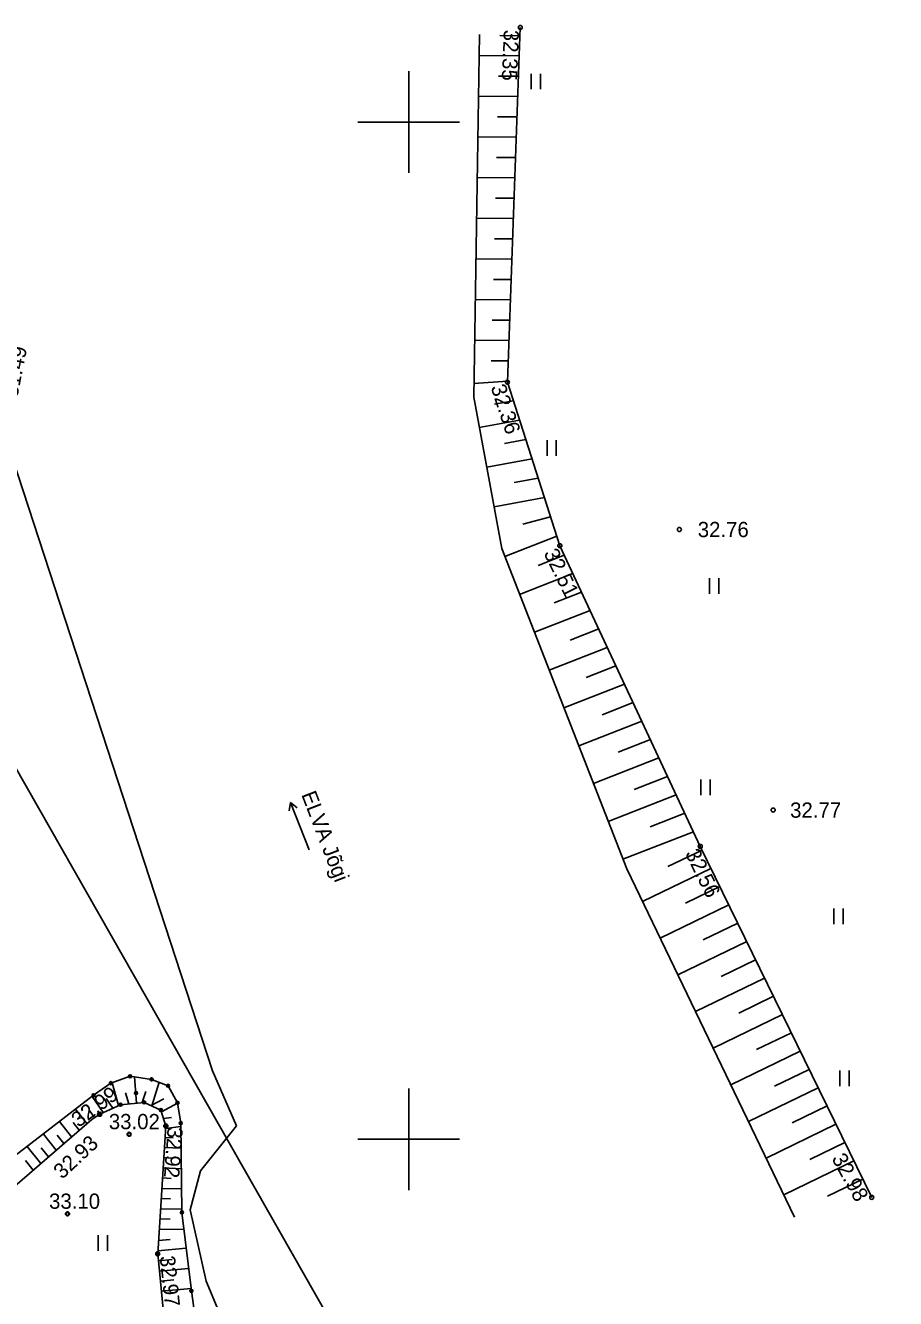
# Model space of a CAD drawing. Extents: x 641898 to 642452, y 6471715 to 6472255.
# Drawn here: x 642081.1 to 642123.9, y 6472192.2 to 6472254.7 of the extents above; entities that cross this region are included whole.
import ezdxf

# ---------------------------------------------------------------- set-up
doc = ezdxf.new("R2010")
doc.units = 0
for name, color, linetype in [('HALJASTUS', 7, 'Continuous'), ('KORGUS-EH2000', 7, 'Continuous'), ('MOOTMPUNKT', 7, 'Continuous'), ('MOOTPIIR', 7, 'Continuous'), ('PIIR', 7, 'Continuous'), ('RELJEEF', 7, 'Continuous'), ('VEEKOGU', 7, 'Continuous'), ('VORK', 7, 'Continuous')]:
    doc.layers.add(name, color=color, linetype=linetype)

msp = doc.modelspace()

# ---------------------------------------------------------------- linework, layer by layer
at = {"layer": 'HALJASTUS'}
for p, q in [((642084.725, 6472195.282), (642084.725, 6472194.521)), ((642085.18, 6472195.282), (642085.18, 6472194.521))]:
    msp.add_line(p, q, dxfattribs=at)
for points in [[(642106.022, 6472252.368), (642106.022, 6472251.607)], [(642106.478, 6472252.368), (642106.478, 6472251.607)], [(642106.798, 6472234.354), (642106.798, 6472233.593)], [(642107.253, 6472234.354), (642107.253, 6472233.593)], [(642114.791, 6472227.575), (642114.791, 6472226.814)], [(642115.246, 6472227.575), (642115.246, 6472226.814)], [(642114.361, 6472217.678), (642114.361, 6472216.917)], [(642114.816, 6472217.678), (642114.816, 6472216.917)], [(642120.901, 6472211.334), (642120.901, 6472210.573)], [(642121.357, 6472211.334), (642121.357, 6472210.573)], [(642121.201, 6472203.375), (642121.201, 6472202.613)], [(642121.656, 6472203.375), (642121.656, 6472202.613)]]:
    msp.add_lwpolyline(points, dxfattribs=at)
at = {"layer": 'KORGUS-EH2000'}
for centre in [(642105.483, 6472254.646), (642104.852, 6472237.213), (642113.31, 6472229.97), (642107.43, 6472229.174), (642117.918, 6472216.179), (642114.333, 6472214.393), (642084.8, 6472201.227), (642088.054, 6472200.65), (642086.247, 6472200.243), (642122.766, 6472197.142), (642083.217, 6472196.331), (642087.656, 6472194.367)]:
    msp.add_circle(centre, 0.1, dxfattribs=at)
at = {"layer": 'MOOTMPUNKT'}
for centre in [(642085.35, 6472202.756), (642086.296, 6472203.094), (642087.356, 6472202.943), (642088.165, 6472202.627), (642084.499, 6472202.158), (642086.586, 6472202.271), (642085.827, 6472201.697), (642086.987, 6472201.809), (642087.81, 6472201.434), (642088.626, 6472201.789), (642084.8, 6472201.227), (642088.054, 6472200.65), (642088.789, 6472200.791), (642086.247, 6472200.243), (642083.217, 6472196.331), (642088.842, 6472196.403), (642087.656, 6472194.367), (642089.31, 6472192.543)]:
    msp.add_circle(centre, 0.075, dxfattribs=at)
at = {"layer": 'MOOTPIIR'}
msp.add_lwpolyline([(642014.306, 6472085.384), (642027.67, 6472104.979), (642055.501, 6472084.843), (642081.563, 6472094.262), (642123.938, 6472142.273), (642065.721, 6472244.475), (642008.922, 6472196.948), (642003.347, 6472200.453), (641979.65, 6472162.756), (641979.65, 6472162.756), (641986.045, 6472158.736), (642004.269, 6472142.365), (641987.048, 6472123.488), (641970.482, 6472097.889), (641986.758, 6472084.396)], close=True, dxfattribs=at)
at = {"layer": 'PIIR'}
for p, q in [((642078.35, 6472240.08), (642090.34, 6472203.36)), ((642090.34, 6472203.36), (642091.53, 6472200.66)), ((642091.53, 6472200.66), (642089.75, 6472198.45)), ((642089.75, 6472198.45), (642089.25, 6472196.53)), ((642089.25, 6472196.53), (642090.03, 6472193.03)), ((642090.03, 6472193.03), (642091.5, 6472189.54))]:
    msp.add_line(p, q, dxfattribs=at)
at = {"layer": 'RELJEEF'}
for p, q in [((642085.733, 6472201.654), (642085.409, 6472202.777)), ((642086.613, 6472201.773), (642086.51, 6472203.063)), ((642087.362, 6472201.638), (642087.73, 6472202.797)), ((642084.977, 6472201.308), (642084.434, 6472202.108)), ((642085.439, 6472201.519), (642085.116, 6472201.994)), ((642086.229, 6472201.736), (642086.072, 6472202.282)), ((642086.889, 6472201.8), (642087.065, 6472202.353)), ((642087.336, 6472201.65), (642087.959, 6472201.98)), ((642084.175, 6472200.774), (642083.615, 6472201.477)), ((642084.541, 6472201.061), (642084.289, 6472201.431)), ((642087.836, 6472201.349), (642088.629, 6472201.769)), ((642083.418, 6472200.119), (642082.822, 6472200.867)), ((642083.796, 6472200.446), (642083.494, 6472200.826)), ((642087.941, 6472201.012), (642088.334, 6472201.066)), ((642082.662, 6472199.464), (642082.029, 6472200.257)), ((642083.04, 6472199.792), (642082.712, 6472200.203)), ((642088.019, 6472200.093), (642088.417, 6472200.073)), ((642088.046, 6472200.521), (642088.791, 6472200.625)), ((642081.906, 6472198.81), (642081.236, 6472199.646)), ((642082.284, 6472199.137), (642081.93, 6472199.579)), ((642087.987, 6472199.594), (642088.804, 6472199.553)), ((642081.527, 6472198.482), (642081.15, 6472198.954)), ((642087.956, 6472199.095), (642088.367, 6472199.075)), ((642087.924, 6472198.596), (642088.816, 6472198.551)), ((642087.86, 6472197.584), (642088.828, 6472197.567)), ((642087.892, 6472198.097), (642088.317, 6472198.076)), ((642087.828, 6472197.085), (642088.289, 6472197.076)), ((642087.797, 6472196.585), (642088.84, 6472196.566)), ((642087.765, 6472196.086), (642088.271, 6472196.077)), ((642087.698, 6472195.025), (642088.266, 6472195.077)), ((642087.733, 6472195.586), (642088.944, 6472195.564)), ((642087.666, 6472194.52), (642089.055, 6472194.647)), ((642087.69, 6472194.021), (642088.357, 6472194.081)), ((642087.738, 6472193.523), (642089.175, 6472193.654)), ((642087.786, 6472193.025), (642088.448, 6472193.085)), ((642087.834, 6472192.528), (642089.296, 6472192.661))]:
    msp.add_line(p, q, dxfattribs=at)
for points in [[(642122.766, 6472197.142), (642114.333, 6472214.393), (642107.43, 6472229.174), (642104.852, 6472237.213), (642105.483, 6472254.646)], [(642105.468, 6472254.244), (642104.47, 6472254.26)], [(642105.432, 6472253.245), (642103.455, 6472253.276)], [(642105.396, 6472252.246), (642104.418, 6472252.261)], [(642105.36, 6472251.246), (642103.424, 6472251.277)], [(642105.324, 6472250.247), (642104.366, 6472250.262)], [(642105.288, 6472249.248), (642103.392, 6472249.277)], [(642105.251, 6472248.248), (642104.314, 6472248.263)], [(642105.215, 6472247.249), (642103.361, 6472247.278)], [(642105.179, 6472246.249), (642104.262, 6472246.264)], [(642105.143, 6472245.25), (642103.33, 6472245.279)], [(642105.107, 6472244.251), (642104.21, 6472244.265)], [(642105.071, 6472243.251), (642103.298, 6472243.279)], [(642105.034, 6472242.252), (642104.159, 6472242.266)], [(642104.998, 6472241.253), (642103.267, 6472241.28)], [(642104.962, 6472240.253), (642104.107, 6472240.267)], [(642104.926, 6472239.254), (642103.236, 6472239.281)], [(642104.89, 6472238.255), (642104.055, 6472238.268)], [(642104.854, 6472237.255), (642103.202, 6472237.139)], [(642105.144, 6472236.301), (642104.217, 6472236.129)], [(642105.45, 6472235.349), (642103.469, 6472234.982)], [(642105.755, 6472234.397), (642104.703, 6472234.202)], [(642106.061, 6472233.444), (642103.831, 6472233.031)], [(642106.366, 6472232.492), (642105.189, 6472232.274)], [(642106.671, 6472231.54), (642104.192, 6472231.081)], [(642106.977, 6472230.588), (642105.61, 6472230.237)], [(642107.282, 6472229.635), (642104.727, 6472228.638)], [(642107.648, 6472228.707), (642106.369, 6472228.208)], [(642108.071, 6472227.801), (642105.453, 6472226.779)], [(642108.494, 6472226.895), (642107.155, 6472226.372)], [(642108.918, 6472225.989), (642106.178, 6472224.92)], [(642109.341, 6472225.083), (642107.941, 6472224.537)], [(642109.764, 6472224.177), (642106.904, 6472223.061)], [(642110.187, 6472223.271), (642108.727, 6472222.701)], [(642110.61, 6472222.365), (642107.63, 6472221.201)], [(642111.033, 6472221.459), (642109.513, 6472220.865)], [(642111.456, 6472220.553), (642108.355, 6472219.342)], [(642111.88, 6472219.646), (642110.299, 6472219.03)], [(642112.303, 6472218.74), (642109.081, 6472217.483)], [(642112.726, 6472217.834), (642111.085, 6472217.194)], [(642113.149, 6472216.928), (642109.806, 6472215.624)], [(642113.572, 6472216.022), (642111.871, 6472215.358)], [(642113.995, 6472215.116), (642110.532, 6472213.765)], [(642114.422, 6472214.212), (642112.738, 6472213.4)], [(642114.861, 6472213.313), (642111.489, 6472211.688)], [(642115.3, 6472212.415), (642113.612, 6472211.601)], [(642115.739, 6472211.516), (642112.357, 6472209.886)], [(642116.178, 6472210.618), (642114.485, 6472209.802)], [(642116.618, 6472209.72), (642113.226, 6472208.085)], [(642117.057, 6472208.821), (642115.358, 6472208.003)], [(642117.496, 6472207.923), (642114.094, 6472206.283)], [(642117.935, 6472207.024), (642116.232, 6472206.203)], [(642118.374, 6472206.126), (642114.962, 6472204.482)], [(642118.813, 6472205.228), (642117.105, 6472204.404)], [(642119.253, 6472204.329), (642115.831, 6472202.68)], [(642119.692, 6472203.431), (642117.978, 6472202.605)], [(642120.131, 6472202.532), (642116.699, 6472200.878)], [(642120.985, 6472144.502), (642117.979, 6472144.088), (642110.518, 6472146.231), (642105.506, 6472148.417), (642100.785, 6472152.198), (642096.824, 6472156.077), (642094.039, 6472159.656), (642091.756, 6472163.65), (642090.992, 6472167.424), (642088.882, 6472176.556), (642088.445, 6472186.228), (642087.656, 6472194.367), (642088.054, 6472200.65), (642087.81, 6472201.434), (642086.987, 6472201.809), (642085.827, 6472201.697), (642084.8, 6472201.227), (642084.408, 6472200.976), (642075.818, 6472193.541), (642067.331, 6472185.862), (642054.685, 6472174.531), (642049.809, 6472171.194), (642046.347, 6472166.588), (642038.018, 6472156.193)], [(642120.57, 6472201.634), (642118.852, 6472200.806)], [(642121.009, 6472200.736), (642117.568, 6472199.077)], [(642121.448, 6472199.837), (642119.725, 6472199.007)], [(642121.888, 6472198.939), (642118.436, 6472197.275)], [(642122.327, 6472198.04), (642120.598, 6472197.207)]]:
    msp.add_lwpolyline(points, dxfattribs=at)
at = {"layer": 'VEEKOGU'}
for points in [[(642103.471, 6472254.302), (642103.192, 6472236.479), (642104.569, 6472229.044), (642110.717, 6472213.29), (642118.969, 6472196.169)], [(642094.51, 6472216.292), (642094.186, 6472216.549), (642094.126, 6472216.14)], [(642095.108, 6472214.225), (642094.186, 6472216.549)], [(642089.978, 6472187.781), (642089.31, 6472192.543), (642088.842, 6472196.403), (642088.789, 6472200.791), (642088.626, 6472201.789), (642088.165, 6472202.627), (642087.356, 6472202.943), (642086.296, 6472203.094), (642085.35, 6472202.756), (642084.499, 6472202.158), (642059.755, 6472183.114)]]:
    msp.add_lwpolyline(points, dxfattribs=at)
at = {"layer": 'VORK'}
for p, q in [((642100, 6472252.5), (642100, 6472247.5)), ((642097.5, 6472250), (642102.5, 6472250)), ((642100, 6472202.5), (642100, 6472197.5)), ((642097.5, 6472200), (642102.5, 6472200))]:
    msp.add_line(p, q, dxfattribs=at)

# ---------------------------------------------------------------- texts
at = {"layer": 'KORGUS-EH2000'}
for s, rotation, p in [('32.35', 267.57687, (642104.677, 6472254.548)), ('31.49', 78.78116, (642080.751, 6472236.432)), ('32.36', 288.1059, (642104.021, 6472236.972)), ('32.51', 296.26754, (642106.617, 6472228.808)), ('32.56', 296.05129, (642113.574, 6472214.051)), ('32.99', 36.68016, (642083.762, 6472200.551)), ('32.93', 42.86132, (642082.954, 6472198.003)), ('32.92', 265.67378, (642088.147, 6472200.628)), ('32.98', 298.81933, (642120.778, 6472199.056)), ('32.97', 275.9235, (642087.751, 6472194.24))]:
    msp.add_text(s, height=0.75, rotation=rotation, dxfattribs=at).set_placement(p)
for s, p in [('32.76', (642114.21, 6472229.595)), ('32.77', (642118.753, 6472215.804)), ('33.02', (642085.249, 6472200.493)), ('33.10', (642082.31, 6472196.581))]:
    msp.add_text(s, height=0.75, dxfattribs=at).set_placement(p)
at = {"layer": 'VEEKOGU'}
msp.add_text('ELVA Jõgi', height=0.75, rotation=291.09375, dxfattribs=at).set_placement((642094.704, 6472216.943))

doc.saveas('drawing.dxf')
